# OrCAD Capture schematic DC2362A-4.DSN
size Custom; title: 3A, 0.95V-10V VERY LOW DROPOUT LINEAR REGULATOR; rev: 4; note: DC2362A
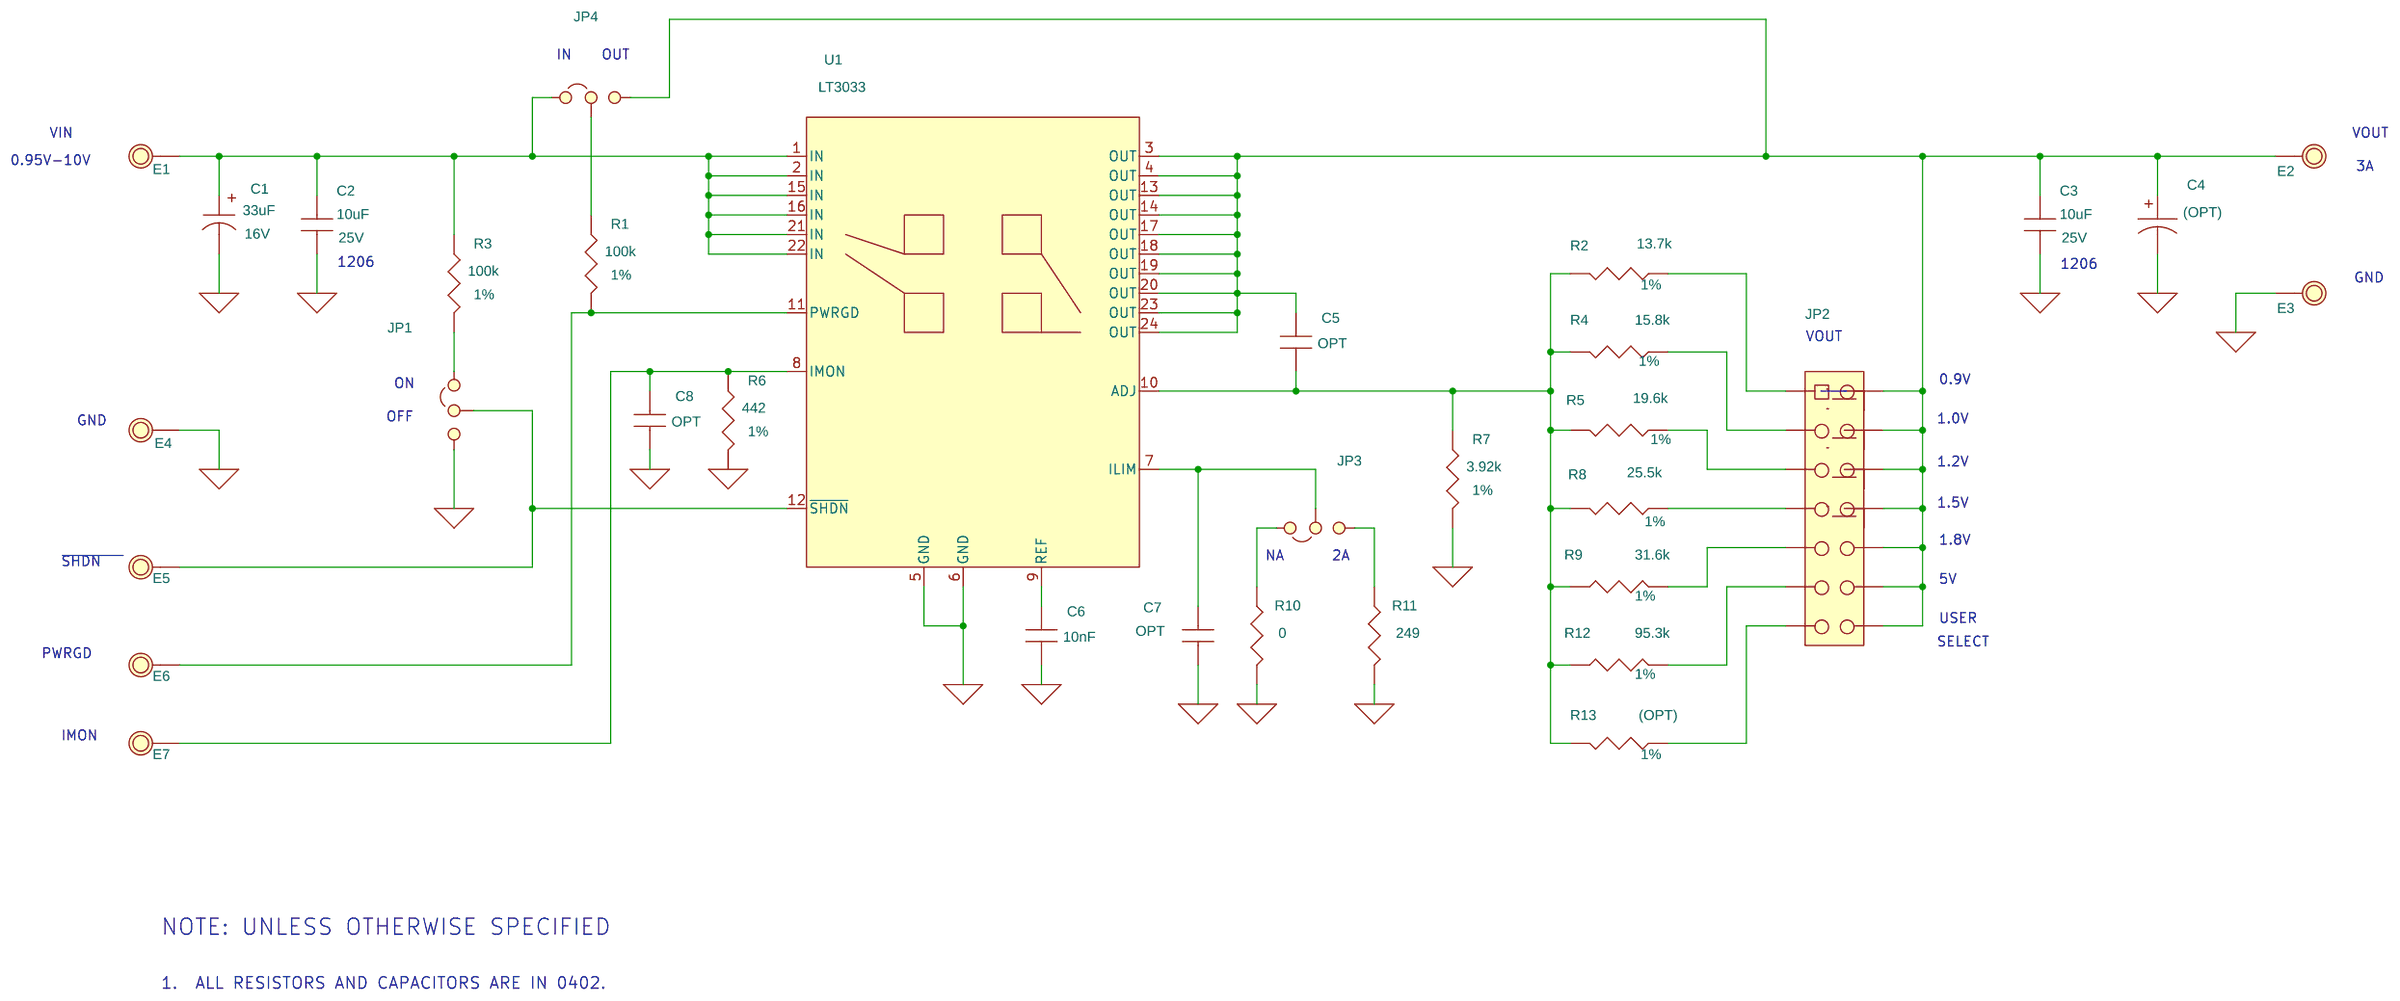
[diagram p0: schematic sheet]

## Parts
C1  33uF  [CAP6032]
C2  10uF  [CAP1206]
C3  10uF  [CAP1206]
C4  (OPT)  [CAP7343]
C5  OPT  [0402]
C6  10nF  [0402]
C7  OPT  [0402]
C8  OPT  [0402]
E1  Testpoint  [MM/2501]
E2  Testpoint  [MM/2501]
E3  Testpoint  [MM/2501]
E4  Testpoint  [MM/2501]
E5  Testpoint  [MM/2501]
E6  Testpoint  [MM/2501]
E7  Testpoint  [MM/2501]
JP1  JP3X1/079\NO\23  [JP3X1/079]
JP2  JP7X2/079  [JP7X2/079]
JP3  JP3X1/079\NO\23  [JP3X1/079]
JP4  JP3X1/079\NO\23  [JP3X1/079]
R1  100k  [0402]
R2  13.7k  [0402]
R3  100k  [0402]
R4  15.8k  [0402]
R5  19.6k  [0402]
R6  442  [0402]
R7  3.92k  [0402]
R8  25.5k  [0402]
R9  31.6k  [0402]
R10  0  [0402]
R11  249  [0402]
R12  95.3k  [0402]
R13  (OPT)  [0402]
U1  LT3033  [UDC-3x4-LT3033]

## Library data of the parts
C1 = CAP+6032: 1ST PART FIELD: 16V
C2 C3 = CAP1206: 1ST PART FIELD: 25V
C4 = CAP__1: 1ST PART FIELD: V; 5TH PART FIELD: 7343
C5-C8 = CAP0402
E1-E7 = MillMax-2501
JP1 JP3 JP4 = JP3X1_079_NO_23
JP2 = JP7X2_079
R1-R13 = AAC-0402: 2ND PART FIELD: 1%
U1 = LT3022EDHC_9

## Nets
GND_SIGNAL: C1.2 C2.2 C3.2 C4.2 C6.2 C7.2 C8.2 E3.1 E4.1 JP1.1 R6.2 R7.2 R10.2 R11.2 U1.5(GND) U1.6(GND)
N00461: C1.1 C2.1 E1.1 JP4.3 R3.1 U1.1(IN) U1.2(IN) U1.15(IN) U1.16(IN) U1.21(IN) U1.22(IN)
N00744: JP1.3 R3.2
N03420: C5.2 R2.2 R4.2 R5.2 R7.1 R8.2 R9.1 R12.1 R13.2 U1.10(ADJ)
N03622: C3.1 C4.1 C5.1 E2.1 JP2.2 JP2.4 JP2.6 JP2.8 JP2.10 JP2.12 JP2.14 JP4.1 U1.3(OUT) U1.4(OUT) U1.13(OUT) U1.14(OUT) U1.17(OUT) U1.18(OUT) U1.19(OUT) U1.20(OUT) U1.23(OUT) U1.24(OUT)
N16477033: E5.1 JP1.2 U1.12(~{SHDN})
N16483036: JP2.13 R13.1
N16483258: JP2.3 R4.1
N16483262: JP2.9 R9.2
N16487159: JP2.7 R8.1
N16500748: JP2.5 R5.1
N16501607: JP2.1 R2.1
N16518551: JP2.11 R12.2
N16518865: C6.1 U1.9(REF)
N16519583: E6.1 R1.2 U1.11(PWRGD)
N16519620: C8.1 E7.1 R6.1 U1.8(IMON)
N16523293: C7.1 JP3.2 U1.7(ILIM)
N16523379: JP3.3 R10.1
N16523618: JP3.1 R11.1
N16526195: JP4.2 R1.1

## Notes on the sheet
- IN
- OUT
- VIN
- VOUT
- 0.95V-10V
- 3A
- 1206
- 1206
- GND
- VOUT
- ON
- 0.9V
- OFF
- GND
- 1.0V
- 1.2V
- 1.5V
- NA
- 2A
- 1.8V
- SHDN
- 5V
- USER
- SELECT
- PWRGD
- IMON
- NOTE: UNLESS OTHERWISE SPECIFIED
- 1.  ALL RESISTORS AND CAPACITORS ARE IN 0402.
